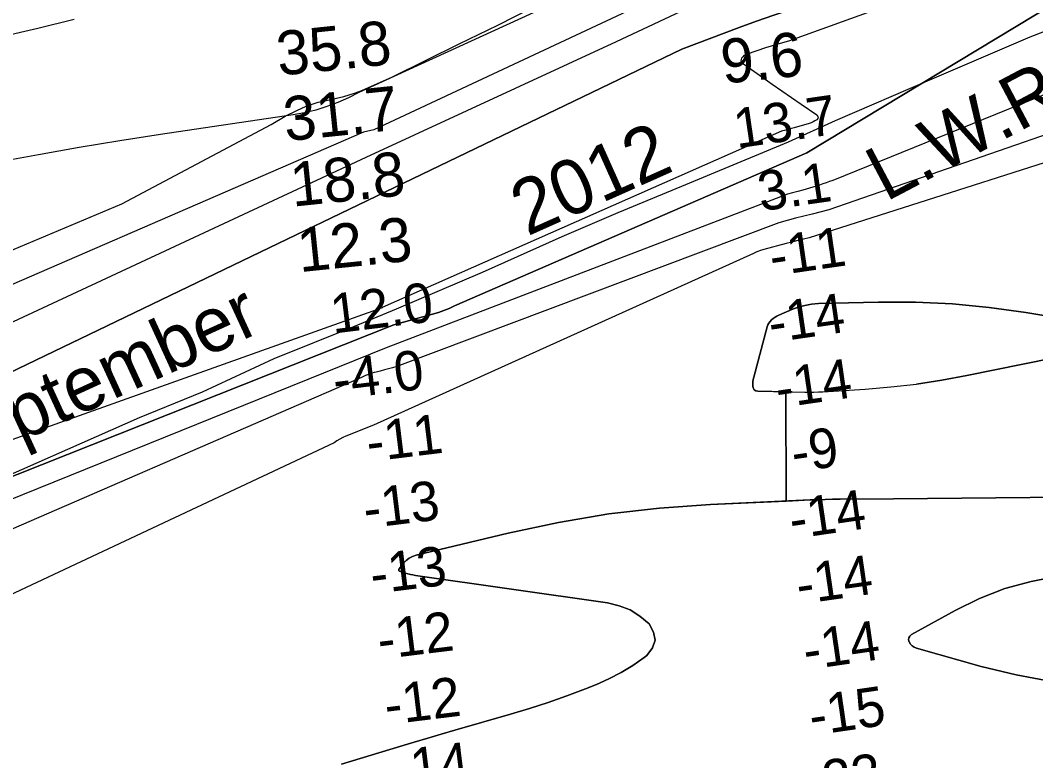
# Model space of a CAD drawing. Extents: x 3219052 to 3256913, y 800770 to 826146.
# Drawn here: x 3226376 to 3227918, y 816190 to 817315 of the extents above; entities that cross this region are included whole.
import ezdxf

# ---------------------------------------------------------------- set-up
doc = ezdxf.new("R2010")
doc.units = 0
for name, color, linetype in [('V-RIVR-EDGE', 7, 'Continuous'), ('V-RIVR-IDEN', 7, 'Continuous'), ('V-RIVR-RANG', 7, 'Continuous'), ('V-SITE-VEGE', 7, 'Continuous'), ('V-TOPO-DPTH', 7, 'Continuous'), ('V-TOPO-MAJR', 7, 'Continuous'), ('V-TOPO-MINR', 7, 'Continuous'), ('V-TOPO-WATR', 7, 'Continuous'), ('V-TOPO-WATR-IDEN', 7, 'Continuous')]:
    doc.layers.add(name, color=color, linetype=linetype)

msp = doc.modelspace()

# ---------------------------------------------------------------- linework, layer by layer
at = {"layer": 'V-RIVR-EDGE'}
msp.add_lwpolyline([(3227993.8, 817322), (3227908.5, 817288.7), (3227756.6, 817223.4), (3227613, 817161.6), (3227541.7, 817129.2), (3227379.8, 817062.2), (3227283.2, 817022.1), (3227197.9, 816985.8), (3227076.9, 816931.3), (3226946.8, 816875.5), (3226881.6, 816848.7), (3226761, 816800.4), (3226652.2, 816749.8), (3226556.5, 816710.4), (3226290.2, 816593.3)], dxfattribs=at)
at = {"layer": 'V-SITE-VEGE'}
for p, q in [((3227101.1, 817307.3), (3227336.2, 817427.5)), ((3227042.2, 817278.7), (3227101.1, 817307.3)), ((3226941.2, 817228.8), (3227042.2, 817278.7)), ((3226894.3, 817207.8), (3226941.2, 817228.8)), ((3226883.1, 817203.8), (3226894.3, 817207.8)), ((3226828.3, 817190.3), (3226844.7, 817193.8)), ((3226844.7, 817193.8), (3226867.1, 817198.7)), ((3226867.1, 817198.7), (3226883.1, 817203.8)), ((3226778.1, 817168.7), (3226795.9, 817177.5)), ((3226795.9, 817177.5), (3226810.1, 817184.2)), ((3226810.1, 817184.2), (3226828.3, 817190.3)), ((3226756.6, 817156.1), (3226778.1, 817168.7)), ((3226530, 817035.8), (3226756.6, 817156.1)), ((3226356.8, 816962.9), (3226530, 817035.8))]:
    msp.add_line(p, q, dxfattribs=at)
at = {"layer": 'V-TOPO-DPTH'}
for points in [[(3226275.8, 816738.9), (3227380.4, 817270.8), (3227467.5, 817303.5), (3227493.8, 817313.1), (3227520.1, 817322.4), (3227546.6, 817331.3), (3227573.2, 817339.9), (3227598.4, 817347.9), (3227612.4, 817352.5), (3227626.3, 817357.4), (3227640.1, 817362.7), (3227653.8, 817368.2), (3227667.4, 817373.8), (3227681.1, 817379.4), (3227694.8, 817384.9), (3227708.5, 817390.3), (3227770.1, 817414.5), (3227814.8, 817431.7), (3227859.6, 817448.6), (3227904.6, 817464.9), (3227949.8, 817480.8)], [(3226294, 816593.9), (3226942.9, 816851.8), (3226957.6, 816855.9), (3227010.7, 816870.7), (3227019, 816873.5), (3227027.2, 816876.8), (3227034.9, 816880.9), (3227570.1, 817113.1), (3228117.6, 817444.2)], [(3228117.6, 817444.2), (3227570.1, 817113.1), (3227034.9, 816880.9), (3227027.2, 816876.8), (3227019, 816873.5), (3227010.7, 816870.7), (3226957.6, 816855.9), (3226942.9, 816851.8), (3226294, 816593.9)], [(3228208.5, 817236.1), (3227603.6, 817026.4), (3227578.2, 817020.1), (3227552.8, 817013.7), (3227527.5, 817007), (3226947.4, 816788.6), (3226941.2, 816786.8), (3226934.9, 816785.1), (3226928.6, 816783.4), (3226922.3, 816781.7), (3226916.4, 816780.2), (3226913, 816779.3), (3226909.7, 816778.3), (3226906.5, 816777.2), (3226903.2, 816776), (3226900, 816774.8), (3226896.9, 816773.4), (3226893.8, 816771.9), (3226254.4, 816494.2)], [(3228208.5, 817236.1), (3227603.6, 817026.4), (3227578.2, 817020.1), (3227552.8, 817013.7), (3227527.5, 817007), (3226947.4, 816788.6), (3226941.2, 816786.8), (3226934.9, 816785.1), (3226928.6, 816783.4), (3226922.3, 816781.7), (3226916.4, 816780.2), (3226913, 816779.3), (3226909.7, 816778.3), (3226906.5, 816777.2), (3226903.2, 816776), (3226900, 816774.8), (3226896.9, 816773.4), (3226893.8, 816771.9), (3226254.4, 816494.2)], [(3227538, 816750.2), (3227495.6, 816751), (3227492.7, 816751.7), (3227490.4, 816753.1), (3227488.9, 816755.4), (3227488, 816758.2), (3227488, 816761.8), (3227488.2, 816765.3), (3227488.7, 816768.8), (3227489.5, 816772.2), (3227510, 816848.7), (3227511.1, 816851.7), (3227512.5, 816854.5), (3227514.4, 816857.1), (3227516.6, 816859.4), (3227519.1, 816861.4), (3227521.8, 816863.3), (3227524.6, 816864.9), (3227527.5, 816866.4), (3227547.2, 816875.1), (3227557, 816878.7), (3227567, 816881.5), (3227577.2, 816883.2), (3227587.6, 816884.1), (3227679, 816886.4), (3227735.2, 816886.2), (3227791.2, 816883.8), (3227846.9, 816878.3), (3227902.5, 816870.6), (3228000.4, 816854.2)], [(3228000.4, 816854.2), (3227902.5, 816870.6), (3227846.9, 816878.3), (3227791.2, 816883.8), (3227735.2, 816886.2), (3227679, 816886.4), (3227587.6, 816884.1), (3227577.2, 816883.2), (3227567, 816881.5), (3227557, 816878.7), (3227547.2, 816875.1), (3227527.5, 816866.4), (3227524.6, 816864.9), (3227521.8, 816863.3), (3227519.1, 816861.4), (3227516.6, 816859.4), (3227514.4, 816857.1), (3227512.5, 816854.5), (3227511.1, 816851.7), (3227510, 816848.7), (3227489.5, 816772.2), (3227488.7, 816768.8), (3227488.2, 816765.3), (3227488, 816761.8), (3227488, 816758.2), (3227488.9, 816755.4), (3227490.4, 816753.1), (3227492.7, 816751.7), (3227495.6, 816751), (3227566.9, 816749.7), (3227573.8, 816749.6), (3227580.7, 816749.7), (3227587.6, 816749.9), (3227594.5, 816750.3), (3227658.7, 816754.3), (3227697.6, 816757.5), (3227736.4, 816761.8)], [(3227985.9, 816810.1), (3227813.3, 816774.8), (3227774.9, 816767.8), (3227736.4, 816761.8)], [(3227736.4, 816761.8), (3227774.9, 816767.8), (3227813.3, 816774.8), (3227985.9, 816810.1)], [(3226863.5, 816184.6), (3226953.5, 816211.9), (3226973.9, 816218.1), (3226994.4, 816224.1), (3227014.9, 816230.1), (3227035.4, 816236), (3227120.4, 816260.3), (3227149.1, 816269), (3227177.6, 816278.2), (3227205.8, 816288.3), (3227233.8, 816299), (3227250.5, 816305.7), (3227269.6, 816314.2), (3227288.2, 816323.7), (3227305.9, 816334.6), (3227323.1, 816346.5), (3227327.1, 816349.5), (3227335.7, 816361), (3227339.9, 816372.9), (3227337.4, 816385.2), (3227330.6, 816397.9), (3227316.6, 816409.3), (3227301.7, 816418.7), (3227285.2, 816425.1), (3227267.7, 816429.4), (3226975.8, 816471.2), (3226971.9, 816471.9), (3226968.1, 816472.7), (3226964.3, 816473.7), (3226960.6, 816474.8), (3226951.4, 816477.7), (3226951, 816478), (3226950.7, 816478.3), (3226950.5, 816478.6), (3226950.4, 816479.1), (3226950.8, 816480.6), (3226951.1, 816481), (3226957.8, 816489.6), (3226961.9, 816493.7), (3226966.3, 816497.3), (3226971.4, 816499.8), (3226976.8, 816501.8), (3227116.7, 816535.6), (3227192.8, 816551.6), (3227269.3, 816564.7), (3227346.5, 816573.4), (3227424, 816579.1), (3227538.6, 816584.2), (3227538, 816750.2)], [(3227547.7, 816750), (3227538, 816750.2), (3227538.6, 816584.2), (3227548.3, 816584.6), (3227575.4, 816585.8), (3227586.7, 816586.2), (3227598, 816586.6), (3227609.3, 816586.8), (3227620.6, 816587), (3227701.7, 816587.8), (3227753.5, 816588.3), (3227805.4, 816588.8), (3227857.2, 816589.3), (3227909.1, 816589.8), (3228244.5, 816593.1)], [(3226863.5, 816184.6), (3226953.5, 816211.9), (3226973.9, 816218.1), (3226994.4, 816224.1), (3227014.9, 816230.1), (3227035.4, 816236), (3227120.4, 816260.3), (3227149.1, 816269), (3227177.6, 816278.2), (3227205.8, 816288.3), (3227233.8, 816299), (3227250.5, 816305.7), (3227269.6, 816314.2), (3227288.2, 816323.7), (3227305.9, 816334.6), (3227323.1, 816346.5), (3227327.1, 816349.5), (3227335.7, 816361), (3227339.9, 816372.9), (3227337.4, 816385.2), (3227330.6, 816397.9), (3227316.6, 816409.3), (3227301.7, 816418.7), (3227285.2, 816425.1), (3227267.7, 816429.4), (3226975.8, 816471.2), (3226971.9, 816471.9), (3226968.1, 816472.7), (3226964.3, 816473.7), (3226960.6, 816474.8), (3226951.4, 816477.7), (3226951, 816478), (3226950.7, 816478.3), (3226950.5, 816478.6), (3226950.4, 816479.1), (3226950.8, 816480.6), (3226951.1, 816481), (3226957.8, 816489.6), (3226961.9, 816493.7), (3226966.3, 816497.3), (3226971.4, 816499.8), (3226976.8, 816501.8), (3227116.7, 816535.6), (3227192.8, 816551.6), (3227269.3, 816564.7), (3227346.5, 816573.4), (3227424, 816579.1), (3227575.4, 816585.8), (3227586.7, 816586.2), (3227598, 816586.6), (3227609.3, 816586.8), (3227620.6, 816587), (3227701.7, 816587.8), (3227753.5, 816588.3), (3227805.4, 816588.8), (3227857.2, 816589.3), (3227909.1, 816589.8), (3228244.5, 816593.1)], [(3227951.3, 816470.2), (3227910.6, 816462.1), (3227870.9, 816451.2), (3227832.5, 816436), (3227795.2, 816417.9), (3227729, 816381.3), (3227726.5, 816379), (3227724.9, 816376.4), (3227724.7, 816373.4), (3227725.4, 816370.1), (3227727.5, 816366.8), (3227730, 816364.1), (3227733.1, 816362.1), (3227736.6, 816360.5), (3227834.6, 816332.7), (3227887.8, 816320), (3227941.4, 816310.1)], [(3227951.3, 816470.2), (3227910.6, 816462.1), (3227870.9, 816451.2), (3227832.5, 816436), (3227795.2, 816417.9), (3227729, 816381.3), (3227726.5, 816379), (3227724.9, 816376.4), (3227724.7, 816373.4), (3227725.4, 816370.1), (3227727.5, 816366.8), (3227730, 816364.1), (3227733.1, 816362.1), (3227736.6, 816360.5), (3227834.6, 816332.7), (3227887.8, 816320), (3227941.4, 816310.1)]]:
    msp.add_lwpolyline(points, dxfattribs=at)
at = {"layer": 'V-TOPO-MAJR'}
msp.add_lwpolyline([(3227449.3, 817461.2), (3226889.7, 817204.8), (3226874, 817196.8), (3226857.9, 817189.6), (3226841.4, 817183.5), (3226824.7, 817178.2), (3226807.6, 817174.1), (3226790.4, 817170.9), (3226588.8, 817141), (3226526.9, 817131.4), (3226465.1, 817121.3), (3226403.4, 817110.4), (3226341.8, 817099)], dxfattribs=at)
at = {"layer": 'V-TOPO-MINR'}
for points in [[(3227963.6, 817575.4), (3227913, 817561.3), (3227862.6, 817546.4), (3227812.6, 817530.3), (3227762.9, 817513.3), (3227692.8, 817488.5), (3227678.3, 817483.3), (3227663.8, 817478), (3227649.3, 817472.7), (3227634.8, 817467.3), (3227620.3, 817462.1), (3227605.8, 817457), (3227591.1, 817452.3), (3227576.3, 817447.8), (3227539, 817436.8), (3227523.9, 817432.4), (3227508.8, 817427.9), (3226912.6, 817147.9), (3226896.8, 817144.4), (3226152, 816821.4)], [(3227949.8, 817480.8), (3227904.6, 817464.9), (3227859.6, 817448.6), (3227814.8, 817431.7), (3227770.1, 817414.5), (3227708.5, 817390.3), (3227694.8, 817384.9), (3227681.1, 817379.4), (3227667.4, 817373.8), (3227653.8, 817368.2), (3227640.1, 817362.7), (3227626.3, 817357.4), (3227612.4, 817352.5), (3227598.4, 817347.9), (3227573.2, 817339.9), (3227546.6, 817331.3), (3227520.1, 817322.4), (3227493.8, 817313.1), (3227467.5, 817303.5), (3227380.4, 817270.8), (3226275.8, 816738.9)], [(3227963.7, 817435.4), (3227542.1, 817282.9), (3227533.4, 817280.5), (3227524.7, 817278), (3227516.1, 817275.4), (3227507.5, 817272.6), (3227479.3, 817263.3), (3227476.9, 817262.3), (3227474.7, 817260.9), (3227472.7, 817259.1), (3227471, 817257.1), (3227470.2, 817255), (3227470.1, 817253), (3227472.4, 817249.4), (3227503.3, 817227.5), (3227517.7, 817217.3), (3227532.2, 817207.2), (3227546.7, 817197.1), (3227561.3, 817187.2), (3227585.1, 817171), (3227587.1, 817167.3), (3227586.6, 817165.4), (3227585.2, 817163.5), (3227582.5, 817161.8), (3227579.7, 817160.2), (3227576.8, 817159), (3227573.7, 817157.9), (3227551.1, 817151.4), (3227544.7, 817149.5), (3227538.2, 817147.8), (3227531.8, 817146.1), (3226925.3, 816878), (3226925.3, 816877.9), (3226165, 816606.9)], [(3227402.7, 817339), (3227280.4, 817281.7), (3226900.7, 817106.3), (3226215.6, 816787.2)], [(3226457.7, 817315.6), (3226402.7, 817302.2), (3226347.6, 817289.4)], [(3228154.8, 817292.5), (3227609.7, 817071.4), (3227604.7, 817069.6), (3227599.7, 817067.7), (3227594.6, 817066), (3227589.6, 817064.2), (3227584.5, 817062.5), (3227579.4, 817060.9), (3227574.3, 817059.4), (3227569.1, 817058), (3227564, 817056.6), (3227556.3, 817054.6), (3227548.6, 817052.5), (3227540.9, 817050.3), (3226931.4, 816817.1), (3226185.7, 816515.8)], [(3228208.5, 817236.1), (3227603.6, 817026.4), (3227578.2, 817020.1), (3227552.8, 817013.7), (3227527.5, 817007), (3226947.4, 816788.6), (3226941.2, 816786.8), (3226934.9, 816785.1), (3226928.6, 816783.4), (3226922.3, 816781.7), (3226916.4, 816780.2), (3226913, 816779.3), (3226909.7, 816778.3), (3226906.5, 816777.2), (3226903.2, 816776), (3226900, 816774.8), (3226896.9, 816773.4), (3226893.8, 816771.9), (3226254.4, 816494.2)], [(3228109.7, 817155.4), (3227573.9, 816983.9), (3227565.1, 816981.9), (3227556.3, 816979.8), (3227547.6, 816977.6), (3227538.9, 816975.4), (3227505, 816966.5), (3227499.6, 816964.8), (3227494.3, 816962.7), (3227489.3, 816960.2), (3226912, 816699.6), (3226870.1, 816682.8), (3226865.5, 816680.7), (3226861, 816678.3), (3226856.7, 816675.6), (3226852.5, 816672.6), (3226258.3, 816393.7)], [(3228000.4, 816854.2), (3227902.5, 816870.6), (3227846.9, 816878.3), (3227791.2, 816883.8), (3227735.2, 816886.2), (3227679, 816886.4), (3227587.6, 816884.1), (3227577.2, 816883.2), (3227567, 816881.5), (3227557, 816878.7), (3227547.2, 816875.1), (3227527.5, 816866.4), (3227524.6, 816864.9), (3227521.8, 816863.3), (3227519.1, 816861.4), (3227516.6, 816859.4), (3227514.4, 816857.1), (3227512.5, 816854.5), (3227511.1, 816851.7), (3227510, 816848.7), (3227489.5, 816772.2), (3227488.7, 816768.8), (3227488.2, 816765.3), (3227488, 816761.8), (3227488, 816758.2), (3227488.9, 816755.4), (3227490.4, 816753.1), (3227492.7, 816751.7), (3227495.6, 816751), (3227566.9, 816749.7), (3227573.8, 816749.6), (3227580.7, 816749.7), (3227587.6, 816749.9), (3227594.5, 816750.3), (3227658.7, 816754.3), (3227697.6, 816757.5), (3227736.4, 816761.8)], [(3227736.4, 816761.8), (3227774.9, 816767.8), (3227813.3, 816774.8), (3227985.9, 816810.1)], [(3228244.5, 816593.1), (3227909.1, 816589.8), (3227857.2, 816589.3), (3227805.4, 816588.8), (3227753.5, 816588.3), (3227701.7, 816587.8), (3227620.6, 816587), (3227609.3, 816586.8), (3227598, 816586.6), (3227586.7, 816586.2), (3227575.4, 816585.8), (3227424, 816579.1), (3227346.5, 816573.4), (3227269.3, 816564.7), (3227192.8, 816551.6), (3227116.7, 816535.6), (3226976.8, 816501.8), (3226971.4, 816499.8), (3226966.3, 816497.3), (3226961.9, 816493.7), (3226957.8, 816489.6), (3226951.1, 816481), (3226950.8, 816480.6), (3226950.4, 816479.1), (3226950.5, 816478.6), (3226950.7, 816478.3), (3226951, 816478), (3226951.4, 816477.7), (3226960.6, 816474.8), (3226964.3, 816473.7), (3226968.1, 816472.7), (3226971.9, 816471.9), (3226975.8, 816471.2), (3227267.7, 816429.4), (3227285.2, 816425.1), (3227301.7, 816418.7), (3227316.6, 816409.3), (3227330.6, 816397.9), (3227337.4, 816385.2), (3227339.9, 816372.9), (3227335.7, 816361), (3227327.1, 816349.5), (3227323.1, 816346.5), (3227305.9, 816334.6), (3227288.2, 816323.7), (3227269.6, 816314.2), (3227250.5, 816305.7), (3227233.8, 816299), (3227205.8, 816288.3), (3227177.6, 816278.2), (3227149.1, 816269), (3227120.4, 816260.3), (3227035.4, 816236), (3227014.9, 816230.1), (3226994.4, 816224.1), (3226973.9, 816218.1), (3226953.5, 816211.9), (3226863.5, 816184.6)], [(3227941.4, 816310.1), (3227887.8, 816320), (3227834.6, 816332.7), (3227736.6, 816360.5), (3227733.1, 816362.1), (3227730, 816364.1), (3227727.5, 816366.8), (3227725.4, 816370.1), (3227724.7, 816373.4), (3227724.9, 816376.4), (3227726.5, 816379), (3227729, 816381.3), (3227795.2, 816417.9), (3227832.5, 816436), (3227870.9, 816451.2), (3227910.6, 816462.1), (3227951.3, 816470.2)]]:
    msp.add_lwpolyline(points, dxfattribs=at)
at = {"layer": 'V-TOPO-WATR'}
msp.add_lwpolyline([(3228117.6, 817444.2), (3227570.1, 817113.1), (3227034.9, 816880.9), (3227027.2, 816876.8), (3227019, 816873.5), (3227010.7, 816870.7), (3226957.6, 816855.9), (3226942.9, 816851.8), (3226294, 816593.9)], dxfattribs=at)

# ---------------------------------------------------------------- texts
at = {"layer": 'V-RIVR-IDEN'}
for s, rotation, p in [('2012', 24.1076, (3227145.5, 816986)), (' September', 24.6124, (3226223.8, 816603.9))]:
    msp.add_text(s, height=83, rotation=rotation, dxfattribs=at).set_placement(p)
at = {"layer": 'V-RIVR-RANG'}
for s, height, rotation, p in [('35.8', 67, 5.9083, (3226768.3, 817230.2)), ('9.6', 67, 5.9083, (3227443.1, 817218.1)), ('31.7', 67, 5.9083, (3226778.8, 817130.7)), ('13.7', 60, 8.2697, (3227463.6, 817119.9)), ('18.8', 67, 5.9083, (3226789.3, 817031.3)), ('3.1', 60, 8.2697, (3227500.1, 817024.3)), ('12.3', 67, 5.9083, (3226799.9, 816931.8)), ('-11', 60, 8.2697, (3227517.6, 816925.8)), ('12.0', 60, 6.9954, (3226850.4, 816838.5)), ('-14', 60, 8.2697, (3227516, 816824.6)), ('-4.0', 60, 6.9954, (3226853.9, 816738.2)), ('-14', 60, 8.2697, (3227526.6, 816725.2)), ('-11', 60, 6.9954, (3226904.8, 816643.7)), ('-9', 60, 8.2697, (3227550.7, 816627.7)), ('-13', 60, 6.9954, (3226900.1, 816542.4)), ('-14', 60, 8.2697, (3227547.7, 816526.3)), ('-13', 60, 6.9954, (3226910.6, 816443)), ('-14', 60, 8.2697, (3227558.2, 816426.9)), ('-12', 60, 6.9954, (3226921.6, 816343.6)), ('-14', 60, 8.2697, (3227568.8, 816327.4)), ('-12', 60, 6.9954, (3226932.2, 816244.2)), ('-15', 60, 8.2697, (3227577.7, 816227.7)), ('-14', 60, 6.9954, (3226945.3, 816145)), ('-23', 60, 8.2697, (3227571.8, 816125.9))]:
    msp.add_text(s, height=height, rotation=rotation, dxfattribs=at).set_placement(p)
at = {"layer": 'V-TOPO-WATR-IDEN'}
msp.add_text('L.W.R.P.', height=83, rotation=27.8301, dxfattribs=at).set_placement((3227690.1, 817038.2))

doc.saveas('drawing.dxf')
